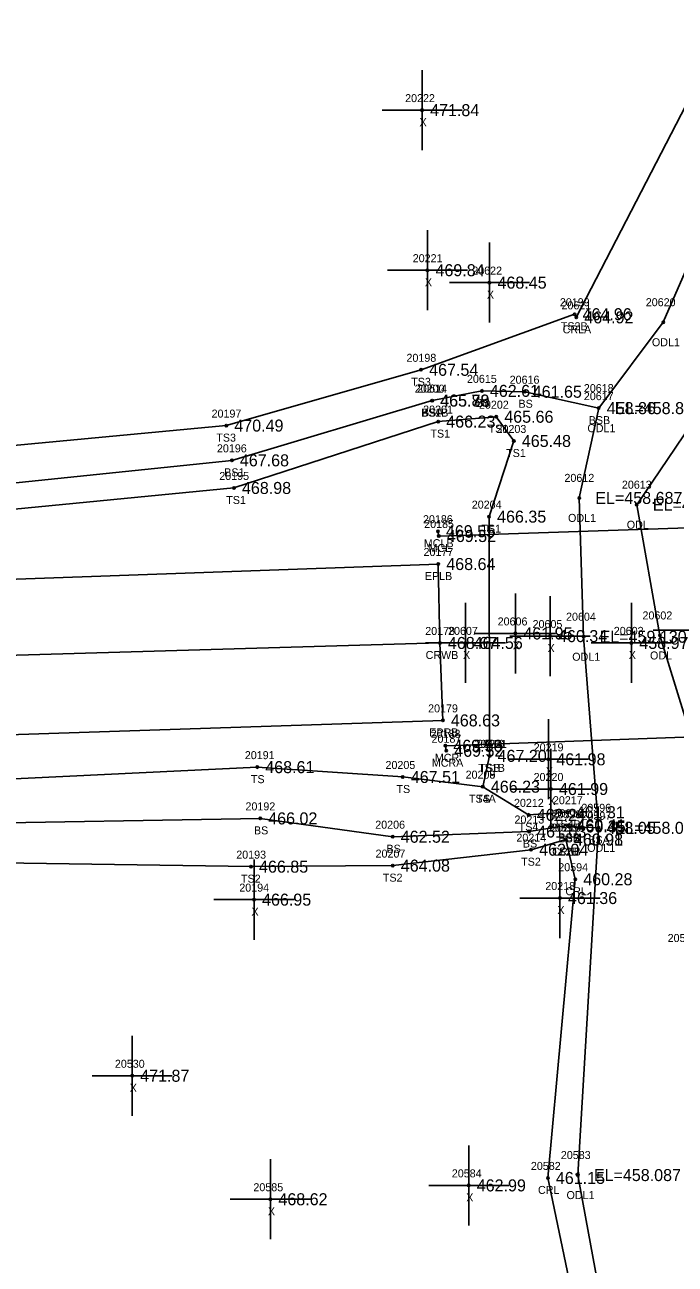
# Model space of a CAD drawing. Extents: x 1785066 to 1786589, y 770293 to 771312.
# Drawn here: x 1785728.1 to 1785809.3, y 770775.9 to 770930.8 of the extents above; entities that cross this region are included whole.
import ezdxf

# ---------------------------------------------------------------- set-up
doc = ezdxf.new("R2010")
doc.units = 0
for name, color, linetype in [('BR_500YR_SCOUR', 7, 'Continuous'), ('RD_DTM_BkLn1', 7, 'Continuous'), ('RD_DTM_BkLn2', 7, 'Continuous'), ('RD_DTM_BkLn_txCode', 7, 'Continuous'), ('RD_EX_Conc_txCode', 7, 'Continuous'), ('RD_EX_H2O', 7, 'Continuous'), ('RD_EX_H2O_txCode', 7, 'Continuous'), ('RD_EX_Misc', 7, 'Continuous'), ('RD_EX_Misc_txCode', 7, 'Continuous'), ('RD_EX_Road', 7, 'Continuous'), ('RD_EX_Road_txCode', 7, 'Continuous'), ('RD_EX_TX_Conc_ELEV', 7, 'Continuous'), ('RD_EX_TX_H2O_ELEV', 7, 'Continuous'), ('RD_EX_TX_Misc_ELEV', 7, 'Continuous'), ('RD_EX_TX_Road_ELEV', 7, 'Continuous'), ('RD_HC_Survey_ELEV', 7, 'Continuous'), ('RD_HC_Survey_txCode', 7, 'Continuous'), ('RD_SMD_Locator', 7, 'Continuous')]:
    doc.layers.add(name, color=color, linetype=linetype)

msp = doc.modelspace()

# ---------------------------------------------------------------- linework, layer by layer
at = {"layer": 'BR_500YR_SCOUR'}
for points in [[(1785824.45, 770868.88), (1785824.54, 770868.38), (1785779.78, 770866.9), (1785779.66, 770867.5)], [(1785780.7, 770840.08), (1785780.59, 770840.7), (1785825.26, 770842.31), (1785825.28, 770841.51)]]:
    msp.add_lwpolyline(points, dxfattribs=at)
for centre in [(1785779.66, 770867.5), (1785779.78, 770866.9), (1785780.59, 770840.7), (1785780.7, 770840.08)]:
    msp.add_circle(centre, 0.15, dxfattribs=at)
at = {"layer": 'RD_DTM_BkLn1'}
msp.add_lwpolyline([(1785082.06, 770851.29), (1785131.3, 770843.85), (1785181.17, 770839.05), (1785231.06, 770837.12), (1785280.99, 770837.06), (1785330.97, 770838.45), (1785380.81, 770840.43), (1785480.56, 770843.94), (1785580.22, 770847.33), (1785679.99, 770850.66), (1785779.91, 770853.54)], dxfattribs=at)
at = {"layer": 'RD_DTM_BkLn2'}
msp.add_line((1785799.71, 770830.45), (1785795.97, 770830.63), dxfattribs=at)
for points in [[(1785219, 770887.48), (1785221.61, 770869.17), (1785226.44, 770862.44), (1785230.83, 770863.64), (1785281.61, 770865.88), (1785330.18, 770866.95), (1785380.62, 770873.53), (1785481.03, 770871.22), (1785579.17, 770869.06), (1785678.49, 770873.66), (1785753.25, 770880.69), (1785777.57, 770887.66), (1785796.72, 770894.6)], [(1785778.94, 770883.82), (1785785.15, 770885.03), (1785790.5, 770884.92), (1785799.74, 770882.87)], [(1785221.18, 770856.06), (1785231.29, 770855.17), (1785280.9, 770855.5), (1785330.48, 770855.32), (1785380.39, 770857.59), (1785481.4, 770861.59), (1785579.34, 770865.13), (1785679.06, 770868.59), (1785753.94, 770876.35), (1785778.96, 770883.81)], [(1785221.33, 770857.68), (1785219.57, 770857.18), (1785219.95, 770853.94), (1785231.29, 770851.96), (1785280.92, 770852.98), (1785330.39, 770854.04), (1785380.75, 770854.37), (1785480.88, 770858.51), (1785579.51, 770861.16), (1785679.28, 770865.65), (1785754.2, 770872.9), (1785779.7, 770881.19), (1785786.95, 770881.8), (1785789.14, 770878.77), (1785786.05, 770869.32), (1785786.11, 770839.44)], [(1785205.07, 770819.03), (1785219.41, 770822.94), (1785230.95, 770822.33), (1785281.39, 770822.23), (1785331.37, 770822.34), (1785381.2, 770825.69), (1785481.76, 770828.75), (1785580.39, 770831.91), (1785680.81, 770834.37), (1785757.11, 770838.03), (1785775.28, 770836.8), (1785785.27, 770835.59), (1785786.11, 770839.44)], [(1785785.27, 770835.59), (1785790.99, 770832.07), (1785795.86, 770832.4)], [(1785217.48, 770818.88), (1785230.53, 770818.92), (1785281.87, 770818.54), (1785331.33, 770820.31), (1785381.53, 770821.9), (1785481.77, 770825.03), (1785580.88, 770828.75), (1785679.45, 770830.28), (1785757.48, 770831.63), (1785774.02, 770829.34), (1785791.05, 770829.99), (1785795.95, 770830.77)], [(1785205.07, 770819.03), (1785218.74, 770813.87), (1785230.3, 770814.87), (1785282.58, 770814.55), (1785331.23, 770817.62), (1785381.61, 770819.76), (1785481.26, 770820.42), (1785579.63, 770825.21), (1785679.72, 770826.75), (1785756.33, 770825.6), (1785774.03, 770825.73), (1785791.3, 770827.72), (1785795.65, 770828.98)]]:
    msp.add_lwpolyline(points, dxfattribs=at)
at = {"layer": 'RD_EX_H2O'}
for points in [[(1785796.94, 770894.21), (1785817.52, 770934.08), (1785841.28, 770978.27), (1785905.84, 771069.13), (1785934.06, 771107.4), (1785932.74, 771138.87), (1785957.1, 771183.16), (1785993.97, 771208.54), (1785990.48, 771236.16), (1786004.55, 771296.27)], [(1785809.1, 770721.92), (1785797.13, 770787.08), (1785799.71, 770830.45), (1785797.84, 770854.32), (1785797.31, 770871.66), (1785799.74, 770882.87), (1785807.79, 770893.6), (1785824.76, 770932.46), (1785830, 770936.66), (1785845.12, 770978.01), (1785907.84, 771068.37), (1785939.25, 771107.77), (1785943.33, 771137.21), (1785960.57, 771178.58), (1785995.85, 771206.75), (1786007.06, 771230.75), (1786010.67, 771288.67)], [(1785820.66, 770730.64), (1785814.87, 770787.58), (1785810.48, 770814.19), (1785812.13, 770827.02), (1785814.82, 770830.33), (1785807.38, 770854.48), (1785804.49, 770870.81), (1785818.14, 770890.97), (1785834.56, 770929.05), (1785857.87, 770974.7), (1785917.08, 771062.46), (1785943.86, 771096.04), (1785952.84, 771134.11), (1785966.16, 771175.54), (1786004.33, 771202.23), (1786012.95, 771230.11), (1786017.56, 771287.45)], [(1785811.86, 770507.25), (1785839.19, 770536.83), (1785857.09, 770560.81), (1785861.18, 770571.03), (1785863.41, 770591.28), (1785864.16, 770601.21), (1785851.56, 770633.71), (1785810.97, 770676.91), (1785806.98, 770721.47), (1785793.39, 770786.72), (1785796.81, 770824.03), (1785795.63, 770828.98)]]:
    msp.add_lwpolyline(points, dxfattribs=at)
at = {"layer": 'RD_EX_Misc'}
for p, q in [((1785777.69, 770915.09), (1785777.69, 770925.09)), ((1785772.69, 770920.09), (1785782.69, 770920.09)), ((1785778.36, 770895.1), (1785778.36, 770905.1)), ((1785786.1, 770893.55), (1785786.1, 770903.55)), ((1785773.36, 770900.1), (1785783.36, 770900.1)), ((1785781.1, 770898.55), (1785791.1, 770898.55)), ((1785789.33, 770849.73), (1785789.33, 770859.73)), ((1785783.12, 770848.55), (1785783.12, 770858.55)), ((1785793.66, 770849.4), (1785793.66, 770859.4)), ((1785803.81, 770848.55), (1785803.81, 770858.55)), ((1785806.55, 770855.13), (1785816.55, 770855.13)), ((1785778.12, 770853.55), (1785788.12, 770853.55)), ((1785784.33, 770854.73), (1785794.33, 770854.73)), ((1785788.66, 770854.4), (1785798.66, 770854.4)), ((1785798.81, 770853.55), (1785808.81, 770853.55)), ((1785793.45, 770834.01), (1785793.45, 770844.01)), ((1785793.77, 770830.3), (1785793.77, 770840.3)), ((1785788.45, 770839.01), (1785798.45, 770839.01)), ((1785788.77, 770835.3), (1785798.77, 770835.3)), ((1785756.71, 770816.48), (1785756.71, 770826.48)), ((1785794.9, 770816.68), (1785794.9, 770826.68)), ((1785751.71, 770821.48), (1785761.71, 770821.48)), ((1785789.9, 770821.68), (1785799.9, 770821.68)), ((1785741.5, 770794.48), (1785741.5, 770804.48)), ((1785736.5, 770799.48), (1785746.5, 770799.48)), ((1785783.51, 770780.79), (1785783.51, 770790.79)), ((1785758.75, 770779.06), (1785758.75, 770789.06)), ((1785778.51, 770785.79), (1785788.51, 770785.79)), ((1785753.75, 770784.06), (1785763.75, 770784.06))]:
    msp.add_line(p, q, dxfattribs=at)
at = {"layer": 'RD_EX_Road'}
for points in [[(1785083.87, 770860.72), (1785132.91, 770853.08), (1785181.89, 770848.53), (1785200.96, 770847.97), (1785215.21, 770848.13), (1785231.38, 770846.18), (1785281.19, 770846.16), (1785330.68, 770847.27), (1785380.41, 770849.82), (1785480.96, 770852.71), (1785580.09, 770856.45), (1785680.2, 770859.84), (1785779.71, 770863.4)], [(1785779.71, 770863.4), (1785779.91, 770853.54), (1785780.28, 770843.87)], [(1785079.74, 770841.1), (1785077.36, 770829.81), (1785127.59, 770822.23), (1785177.27, 770813.99), (1785180.45, 770828), (1785230.74, 770826.87), (1785281.16, 770827.18), (1785331.14, 770828.42), (1785381.03, 770830.27), (1785481.34, 770833.99), (1785580.1, 770837.94), (1785680.6, 770840.57), (1785780.28, 770843.87)]]:
    msp.add_lwpolyline(points, dxfattribs=at)
at = {"layer": 'RD_SMD_Locator'}
for centre in [(1785777.69, 770920.09), (1785778.36, 770900.1), (1785786.1, 770898.55), (1785796.72, 770894.6), (1785796.94, 770894.21), (1785807.79, 770893.6), (1785777.57, 770887.66), (1785785.15, 770885.03), (1785790.5, 770884.92), (1785778.94, 770883.82), (1785778.96, 770883.81), (1785799.74, 770882.87), (1785799.74, 770882.87), (1785779.7, 770881.19), (1785786.95, 770881.8), (1785753.25, 770880.69), (1785789.14, 770878.77), (1785753.94, 770876.35), (1785754.2, 770872.9), (1785797.31, 770871.66), (1785804.49, 770870.81), (1785786.05, 770869.32), (1785779.71, 770863.4), (1785779.91, 770853.54), (1785783.12, 770853.55), (1785789.33, 770854.73), (1785793.66, 770854.4), (1785797.84, 770854.32), (1785803.81, 770853.55), (1785807.38, 770854.48), (1785780.28, 770843.87), (1785786.11, 770839.44), (1785786.11, 770839.44), (1785757.11, 770838.03), (1785793.45, 770839.01), (1785775.28, 770836.8), (1785785.27, 770835.59), (1785785.27, 770835.59), (1785793.77, 770835.3), (1785790.99, 770832.07), (1785795.86, 770832.4), (1785757.48, 770831.63), (1785795.95, 770830.77), (1785795.97, 770830.63), (1785799.71, 770830.45), (1785799.71, 770830.45), (1785774.02, 770829.34), (1785791.05, 770829.99), (1785795.63, 770828.98), (1785795.65, 770828.98), (1785791.3, 770827.72), (1785756.33, 770825.6), (1785774.03, 770825.73), (1785796.81, 770824.03), (1785756.71, 770821.48), (1785794.9, 770821.68), (1785741.5, 770799.48), (1785797.13, 770787.08), (1785783.51, 770785.79), (1785793.39, 770786.72), (1785758.75, 770784.06)]:
    msp.add_circle(centre, 0.15, dxfattribs=at)

# ---------------------------------------------------------------- texts
at = {"layer": 'RD_DTM_BkLn_txCode'}
for s, p in [('20199', (1785794.89, 770895.6)), ('TS3B', (1785795.01, 770892.6)), ('20198', (1785775.74, 770888.66)), ('TS3', (1785776.33, 770885.66)), ('20615', (1785783.29, 770886.03)), ('20616', (1785788.62, 770885.92)), ('20200', (1785776.77, 770884.81)), ('20614', (1785777.08, 770884.82)), ('20617', (1785797.88, 770883.87)), ('20201', (1785777.82, 770882.19)), ('BS', (1785784.37, 770883.03)), ('20202', (1785784.79, 770882.8)), ('BS', (1785789.72, 770882.92)), ('20197', (1785751.41, 770881.69)), ('BS1B', (1785777.55, 770881.81)), ('BSA', (1785777.67, 770881.82)), ('BSB', (1785798.49, 770880.87)), ('TS1', (1785778.73, 770879.19)), ('TS1', (1785785.99, 770879.8)), ('20203', (1785786.98, 770879.77)), ('TS3', (1785752, 770878.69)), ('20196', (1785752.08, 770877.35)), ('TS1', (1785788.18, 770876.77)), ('BS1', (1785752.99, 770874.35)), ('20195', (1785752.37, 770873.9)), ('TS1', (1785753.24, 770870.9)), ('20204', (1785783.89, 770870.32)), ('TS1', (1785785.09, 770867.32)), ('20210', (1785784.24, 770840.44)), ('20211', (1785784.56, 770840.44)), ('20191', (1785755.56, 770839.03)), ('20205', (1785773.12, 770837.8)), ('TS1B', (1785784.68, 770837.44)), ('TSB', (1785784.84, 770837.44)), ('TS', (1785756.32, 770836.03)), ('20208', (1785783.12, 770836.59)), ('20209', (1785783.12, 770836.59)), ('TS', (1785774.49, 770834.8)), ('20192', (1785755.64, 770832.63)), ('TS4A', (1785783.54, 770833.59)), ('TS', (1785784.48, 770833.59)), ('20212', (1785789.16, 770833.07)), ('20217', (1785794.02, 770833.4)), ('20213', (1785789.22, 770830.99)), ('20598', (1785793.85, 770831.63)), ('20216', (1785794.09, 770831.77)), ('20597', (1785797.59, 770831.45)), ('BS', (1785756.7, 770829.63)), ('20206', (1785771.84, 770830.34)), ('TS4', (1785789.75, 770830.07)), ('20215', (1785793.81, 770829.98)), ('TS4B', (1785794.14, 770830.4)), ('20214', (1785789.46, 770828.72)), ('BS', (1785790.27, 770827.99)), ('BSB', (1785794.7, 770828.77)), ('BSB', (1785794.71, 770828.63)), ('BSA', (1785798.44, 770828.45)), ('20193', (1785754.49, 770826.6)), ('20207', (1785771.88, 770826.73)), ('BS', (1785773.24, 770827.34)), ('TS2B', (1785793.93, 770826.98)), ('TS2', (1785790.05, 770825.72)), ('TS2', (1785755.08, 770823.6)), ('TS2', (1785772.79, 770823.73))]:
    msp.add_text(s, height=1, dxfattribs=at).set_placement(p)
at = {"layer": 'RD_EX_Conc_txCode'}
for s, p in [('20186', (1785777.8, 770868.5)), ('20185', (1785777.95, 770867.9)), ('MCLB', (1785777.9, 770865.5)), ('MCL', (1785778.49, 770864.9)), ('20188', (1785778.76, 770841.7)), ('20187', (1785778.87, 770841.08)), ('MCR', (1785779.28, 770838.7)), ('MCRA', (1785778.9, 770838.08))]:
    msp.add_text(s, height=1, dxfattribs=at).set_placement(p)
at = {"layer": 'RD_EX_H2O_txCode'}
for s, p in [('20621', (1785795.09, 770895.21)), ('20620', (1785805.61, 770895.6)), ('CRLA', (1785795.23, 770892.21)), ('ODL1', (1785806.38, 770890.6)), ('20618', (1785797.88, 770884.87)), ('ODL1', (1785798.33, 770879.87)), ('20612', (1785795.46, 770873.66)), ('20613', (1785802.63, 770872.81)), ('ODL1', (1785795.91, 770868.66)), ('ODL', (1785803.24, 770867.81)), ('20604', (1785795.66, 770856.32)), ('20602', (1785805.2, 770856.48)), ('ODL1', (1785796.43, 770851.32)), ('ODL', (1785806.14, 770851.48)), ('20596', (1785797.57, 770832.45)), ('20595', (1785793.51, 770829.98)), ('CRLB', (1785793.93, 770826.98)), ('ODL1', (1785798.3, 770827.45)), ('20594', (1785794.69, 770825.03)), ('CRL', (1785795.58, 770822.03)), ('20586', (1785808.34, 770816.19)), ('20583', (1785795.01, 770789.08)), ('20582', (1785791.27, 770787.72)), ('CRL', (1785792.16, 770784.72)), ('ODL1', (1785795.72, 770784.08))]:
    msp.add_text(s, height=1, dxfattribs=at).set_placement(p)
at = {"layer": 'RD_EX_Misc_txCode'}
for s, p in [('20222', (1785775.57, 770921.09)), ('X', (1785777.37, 770918.09)), ('20221', (1785776.52, 770901.1)), ('20622', (1785783.95, 770899.55)), ('X', (1785778.04, 770898.1)), ('X', (1785785.78, 770896.55)), ('20606', (1785787.12, 770855.73)), ('20607', (1785780.93, 770854.55)), ('20605', (1785791.48, 770855.4)), ('20603', (1785801.62, 770854.55)), ('X', (1785789.01, 770852.73)), ('X', (1785782.8, 770851.55)), ('X', (1785793.35, 770852.4)), ('X', (1785803.49, 770851.55)), ('20219', (1785791.62, 770840.01)), ('X', (1785793.14, 770837.01)), ('20220', (1785791.61, 770836.3)), ('X', (1785793.45, 770833.3)), ('20194', (1785754.87, 770822.48)), ('20218', (1785793.07, 770822.68)), ('X', (1785756.39, 770819.48)), ('X', (1785794.58, 770819.68)), ('20530', (1785739.34, 770800.48)), ('X', (1785741.19, 770797.48)), ('20584', (1785781.4, 770786.79)), ('20585', (1785756.63, 770785.06)), ('X', (1785783.2, 770783.79)), ('X', (1785758.44, 770782.06))]:
    msp.add_text(s, height=1, dxfattribs=at).set_placement(p)
at = {"layer": 'RD_EX_Road_txCode'}
for s, p in [('20177', (1785777.87, 770864.4)), ('EPLB', (1785778.03, 770861.4)), ('20179', (1785778.44, 770844.87)), ('EPRB', (1785778.58, 770841.87))]:
    msp.add_text(s, height=1, dxfattribs=at).set_placement(p)
at = {"layer": 'RD_EX_TX_Conc_ELEV'}
for s, p in [('469.55', (1785780.66, 770866.75)), ('469.52', (1785780.78, 770866.15)), ('469.50', (1785781.59, 770839.95)), ('469.52', (1785781.7, 770839.33))]:
    msp.add_text(s, height=1.5, dxfattribs=at).set_placement(p)
at = {"layer": 'RD_EX_TX_H2O_ELEV'}
for s, p in [('464.92', (1785797.94, 770893.46)), ('EL=458.860', (1785801.74, 770882.12)), ('EL=458.687', (1785799.31, 770870.91)), ('EL=458.619', (1785806.49, 770870.06)), ('EL=459.130', (1785799.84, 770853.57)), ('EL=458.045', (1785801.71, 770829.7)), ('460.91', (1785796.63, 770828.23)), ('460.28', (1785797.81, 770823.28)), ('461.15', (1785794.39, 770785.97)), ('EL=458.087', (1785799.13, 770786.33))]:
    msp.add_text(s, height=1.5, dxfattribs=at).set_placement(p)
at = {"layer": 'RD_EX_TX_Misc_ELEV'}
for s, p in [('471.84', (1785778.69, 770919.34)), ('469.84', (1785779.36, 770899.35)), ('468.45', (1785787.1, 770897.8)), ('464.96', (1785797.72, 770893.85)), ('467.54', (1785778.57, 770886.91)), ('465.78', (1785779.94, 770883.07)), ('465.80', (1785779.96, 770883.06)), ('462.61', (1785786.15, 770884.28)), ('461.65', (1785791.5, 770884.17)), ('458.86', (1785800.74, 770882.12)), ('470.49', (1785754.25, 770879.94)), ('466.23', (1785780.7, 770880.44)), ('465.66', (1785787.95, 770881.05)), ('465.48', (1785790.14, 770878.02)), ('467.68', (1785754.94, 770875.6)), ('468.98', (1785755.2, 770872.15)), ('466.35', (1785787.05, 770868.57)), ('461.95', (1785790.33, 770853.98)), ('460.34', (1785794.66, 770853.65)), ('464.56', (1785784.12, 770852.8)), ('458.97', (1785804.81, 770852.8)), ('467.20', (1785787.11, 770838.69)), ('467.20', (1785787.11, 770838.69)), ('461.98', (1785794.45, 770838.26)), ('468.61', (1785758.11, 770837.28)), ('467.51', (1785776.28, 770836.05)), ('466.23', (1785786.27, 770834.84)), ('466.23', (1785786.27, 770834.84)), ('461.99', (1785794.77, 770834.55)), ('466.02', (1785758.48, 770830.88)), ('462.24', (1785791.99, 770831.32)), ('461.31', (1785796.86, 770831.65)), ('461.03', (1785792.05, 770829.24)), ('460.41', (1785796.95, 770830.02)), ('460.35', (1785796.97, 770829.88)), ('458.05', (1785800.71, 770829.7)), ('462.52', (1785775.02, 770828.59)), ('460.98', (1785796.65, 770828.23)), ('462.04', (1785792.3, 770826.97)), ('466.85', (1785757.33, 770824.85)), ('464.08', (1785775.03, 770824.98)), ('466.95', (1785757.71, 770820.73)), ('461.36', (1785795.9, 770820.93)), ('471.87', (1785742.5, 770798.73)), ('462.99', (1785784.51, 770785.04)), ('468.62', (1785759.75, 770783.31))]:
    msp.add_text(s, height=1.5, dxfattribs=at).set_placement(p)
at = {"layer": 'RD_EX_TX_Road_ELEV'}
for s, p in [('468.64', (1785780.71, 770862.65)), ('468.63', (1785781.28, 770843.12))]:
    msp.add_text(s, height=1.5, dxfattribs=at).set_placement(p)
at = {"layer": 'RD_HC_Survey_ELEV'}
msp.add_text('468.67', height=1.5, dxfattribs=at).set_placement((1785780.91, 770852.79))
at = {"layer": 'RD_HC_Survey_txCode'}
for s, p in [('20178', (1785778.08, 770854.54)), ('CRWB', (1785778.13, 770851.54))]:
    msp.add_text(s, height=1, dxfattribs=at).set_placement(p)

doc.saveas('drawing.dxf')
